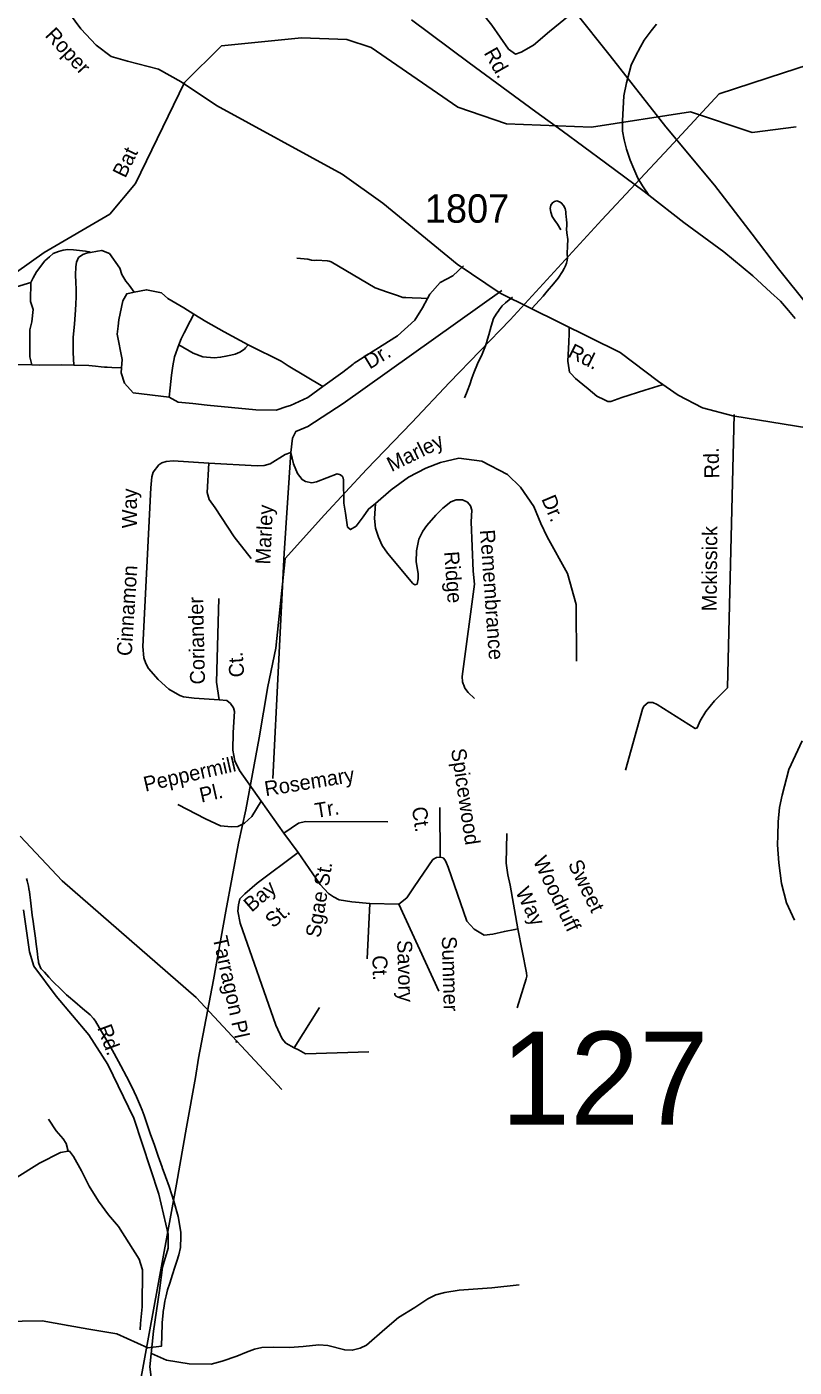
# Model space of a CAD drawing. Extents: x 884530 to 1028605, y 526725 to 653634.
# Drawn here: x 978709 to 982090, y 565783 to 571686 of the extents above; entities that cross this region are included whole.
import ezdxf

# ---------------------------------------------------------------- set-up
doc = ezdxf.new("R2010")
doc.units = 0
for name, color, linetype in [('Exist Boundary Political City Limit New', 7, 'Continuous'), ('Exist Hydrographic Creek Single Shore', 7, 'Continuous'), ('Exist Hydrographic Creek Single Shore Label', 7, 'Continuous'), ('Exist Railroad Mainline', 7, 'Continuous'), ('Exist Road Non-System Type 51', 7, 'Continuous'), ('Exist Road Non-System Type 51 Label', 7, 'Continuous'), ('Exist Road Primary US UnDivided 4 Lane Attributed', 7, 'Continuous'), ('Exist Road Secondary Structure Standard Bridge Number Label', 7, 'Continuous'), ('Exist Road Secondary Type 51 Attributed', 7, 'Continuous'), ('Exist Road Secondary Type 51 Label', 7, 'Continuous'), ('Exist Road Secondary Type 51 Number Label', 7, 'Continuous'), ('Exist Utilities Electrical Transmission Line', 7, 'Continuous'), ('Map Preparation Boundary City Limit Buffer Line', 7, 'Continuous')]:
    doc.layers.add(name, color=color, linetype=linetype)

msp = doc.modelspace()

# ---------------------------------------------------------------- linework, layer by layer
at = {"layer": 'Exist Boundary Political City Limit New'}
for points in [[(979387.1, 566377.1), (979375.6, 566446.4), (979356.9, 566513.9), (979335.4, 566578.2), (979320, 566622.3), (979305.6, 566663), (979305.3, 566663.8), (979287.9, 566712.2), (979269.2, 566764.4), (979253.9, 566808.4), (979239.1, 566852.1), (979225.4, 566891.6), (979216.6, 566914.7), (979209.6, 566933.2), (979192.1, 566974.1), (979171.5, 567017.6), (979148.4, 567062.8), (979123.1, 567110.2), (979093.1, 567164.6), (979065, 567214.5), (979038.2, 567261.5), (979012, 567307), (979002.6, 567319.1), (978987.8, 567334.4), (978953.8, 567363.1), (978920.3, 567392.5), (978891.7, 567414.8), (978883.6, 567422.8), (978861.4, 567444.2), (978821.4, 567483.2), (978805.2, 567501.1), (978785.9, 567523), (978778.8, 567530.7), (978771.4, 567538.1), (978769.3, 567541.8), (978767.4, 567546), (978764.5, 567554), (978762.3, 567560.6), (978760.9, 567565.7), (978759.8, 567571.1), (978758.5, 567578.2), (978757.3, 567586.1), (978755.2, 567603.6), (978753.1, 567625.4), (978750.5, 567646.6), (978746.8, 567673.1), (978739.1, 567723.1), (978736, 567745.3), (978732.4, 567773.7), (978724.8, 567839.8), (978722.2, 567863.7), (978720.5, 567875.9), (978718.3, 567889), (978715.9, 567901.2), (978713.1, 567913.3), (978710.3, 567924.9), (978707.5, 567935.5)], [(978508.9, 565983.2), (978777, 565986.5), (978890.5, 565966.3), (978982.1, 565950), (979105.3, 565930.1), (979242.2, 565868.1), (979301.4, 565875.2), (979303.2, 565923.6), (979305.1, 565972.6), (979305.2, 565977.5), (979309, 566023.9), (979309.3, 566027.6), (979311.7, 566043.1), (979316.4, 566073.2), (979322, 566097.2), (979329.3, 566122.9), (979338.8, 566153.4), (979350.4, 566190.7), (979360.8, 566222.9), (979370.4, 566250.5), (979379.1, 566278.1), (979386, 566310.1), (979386.8, 566358.4), (979387.1, 566374.3), (979387.1, 566377.1)]]:
    msp.add_lwpolyline(points, dxfattribs=at)
at = {"layer": 'Exist Hydrographic Creek Single Shore'}
for points in [[(978596.8, 570558.8), (978785, 570692.8), (979074.3, 570860.9), (979187.5, 570996.4), (979403, 571441.7), (979567.1, 571602.5), (979918.5, 571638.1), (980118.4, 571630.8), (980225.5, 571595.8), (980608.3, 571332.1), (980822.6, 571258.9), (981197.5, 571244.8), (981633.4, 571311.4), (981905.3, 571220.6), (982098.1, 571246.3)], [(979833, 567005.9), (979455.2, 567410.6), (978864.1, 567924.6), (978679.2, 568122)]]:
    msp.add_lwpolyline(points, dxfattribs=at)
at = {"layer": 'Exist Railroad Mainline'}
for points in [[(980403.9, 571717.2), (980657.5, 571528.3), (980952.2, 571311.9), (981067.4, 571227.9), (981258.6, 571087.2), (981428.5, 570961.2), (981449.8, 570944.5), (981603.8, 570825), (981779.4, 570694.8), (981908, 570590.4), (981987.5, 570515.6), (982030.1, 570478.1), (982064.7, 570436.8), (982093.6, 570401.8)], [(981483.9, 571697.9), (981459, 571668.6), (981429.5, 571627.7), (981412.5, 571598.3), (981391.1, 571556.9), (981371.7, 571517.5), (981350.9, 571440.3), (981339, 571382.7), (981333.2, 571272.8), (981333.6, 571226.8), (981340.3, 571188.4), (981350.8, 571148), (981367.3, 571099.4), (981383.9, 571060.9), (981400.5, 571020.1), (981421.2, 570985.5), (981449.8, 570944.5)], [(982125.2, 568541.4), (982066.3, 568414.6), (982037.1, 568301.8), (982025.2, 568248.2)], [(982025.2, 568248.2), (982020, 568184.5), (982018, 568124.5), (982016.8, 568083.7), (982021.8, 568004.4), (982034.1, 567912.8), (982056.4, 567828.6), (982091.1, 567751.8)]]:
    msp.add_lwpolyline(points, dxfattribs=at)
at = {"layer": 'Exist Road Non-System Type 51'}
for p, q in [((979742, 568275.9), (979840.8, 568134.7)), ((980529.3, 568029), (980529.2, 568247.8)), ((979840.8, 568134.7), (979904.6, 568049.5)), ((980220.8, 567824.4), (980207.9, 567581.9)), ((980220.8, 567824.4), (980348, 567822.2)), ((980348, 567822.2), (980523.7, 567438.5)), ((979887.4, 567189.7), (979997.7, 567367))]:
    msp.add_line(p, q, dxfattribs=at)
for points in [[(980934.5, 570445.9), (980968.4, 570482.1), (980983.8, 570499.4), (981002.1, 570521.8), (981028.7, 570553.9), (981049.6, 570579.3), (981069.4, 570609.2), (981076.5, 570621.8), (981082.7, 570633.7), (981087.2, 570645.1), (981089.7, 570657.1), (981090.4, 570670.6), (981089.8, 570687.1), (981090.7, 570721.3), (981092.6, 570749), (981087.8, 570779.4), (981086.1, 570795.6), (981087.8, 570811.1), (981087.8, 570822.7), (981086.1, 570835.9), (981084.7, 570851.3), (981083.9, 570862.9), (981083.2, 570871.5), (981081.5, 570886.1), (981073, 570900.1), (981063.8, 570911.7), (981055.3, 570915.5), (981044.5, 570919.4), (981034.4, 570916.7), (981024.6, 570911.4), (981018, 570901.2), (981015.1, 570886.9), (981017.4, 570870.7), (981022.8, 570851.3), (981035.1, 570832.8), (981046.8, 570816.5), (981062.3, 570792.6)], [(978726.9, 570560.2), (978736.8, 570580.5), (978751.3, 570606.6), (978788.8, 570655.7), (978808.8, 570673.7), (978824.5, 570688), (978847.9, 570697.1), (978868.7, 570703.1), (978889.1, 570705.7), (978914.2, 570704.6), (978940.4, 570701.1), (978966.7, 570697.6), (978974.6, 570696.8), (978984.1, 570695), (978989.5, 570693)], [(978915.9, 570196.1), (978913.4, 570251.5), (978912.4, 570287.3), (978913.1, 570319.9), (978915.6, 570347.5), (978918.9, 570378), (978921.9, 570417.6), (978924.6, 570463), (978926.1, 570498.1), (978925.9, 570530.3), (978924, 570561), (978922.5, 570594.1), (978924.1, 570628.6), (978928, 570650.5), (978937.1, 570669.8), (978955.1, 570684), (978971.5, 570689.9), (978986.4, 570692.5), (978989.5, 570693)], [(978989.5, 570693), (979019.7, 570697.6), (979039.2, 570701.3), (979072.3, 570687.6), (979118.7, 570623.9), (979127.3, 570595), (979144.7, 570566.1), (979160.1, 570548.9), (979181.8, 570517.3)], [(980473.9, 570489.4), (980445.7, 570492), (980406.5, 570492.9), (980378.8, 570493.9), (980371.2, 570493.9), (980365.5, 570494.8), (980342.5, 570502.5), (980298.6, 570517.7), (980243.3, 570536.8), (980049.1, 570650.9), (980040.9, 570654.3), (980032.4, 570656.2), (979986.6, 570658.1), (979975.1, 570657.1), (979963.6, 570658.1), (979947.4, 570662.9), (979897.8, 570667.6)], [(980632.8, 570634), (980585.2, 570589.2), (980530.3, 570560.2), (980483.9, 570508.2), (980473.9, 570489.4)], [(978731, 570197), (978660.4, 570199.8), (978613.4, 570205.4), (978569.3, 570213.7), (978536.8, 570224.4), (978525.2, 570242.3), (978521, 570273.7), (978521.8, 570310.1), (978526.6, 570360.7), (978536.5, 570403.1), (978554.7, 570441.1), (978594.2, 570489), (978644.4, 570528.8), (978663.9, 570540.9), (978726.9, 570560.2)], [(978731, 570197), (978722.4, 570233.4), (978722.4, 570253.6), (978722.4, 570282.5), (978722.4, 570314.4), (978722.4, 570352), (978731, 570386.7), (978736.8, 570441.7), (978725.3, 570476.4), (978725.5, 570510), (978725.8, 570530.6), (978726.9, 570560.2)], [(979126, 570184.7), (979128.1, 570221.4), (979107.3, 570332.9), (979111.1, 570367.3), (979114.2, 570395.7), (979131.6, 570479.4), (979149, 570510.8), (979181.8, 570517.3)], [(979181.8, 570517.3), (979236.2, 570528.2), (979302.4, 570514.3), (979330.4, 570489.9), (979400.1, 570448), (979444.7, 570421)], [(980473.9, 570489.4), (980451.9, 570448.7), (980418.7, 570394.3), (980341.9, 570324.7), (980151.2, 570205.1), (980146.3, 570200.7), (980100.8, 570165.6), (980012.8, 570102.5), (979947.4, 570054.1), (979870.7, 570019.2), (979854.9, 570013.9), (979808, 569998.2), (979717.4, 569999.1), (979503.4, 570019.3), (979439.8, 570028), (979376.1, 570033.8), (979335.8, 570055.8)], [(980802.4, 570524.5), (980103.3, 570027.6), (979947, 569925.7), (979893.9, 569903.6), (979879.4, 569874.7), (979871.4, 569811.4)], [(980848.5, 570495.4), (980818, 570471.2), (980803.6, 570457.6), (980790.4, 570440.6), (980785.3, 570432.6), (980780.4, 570425.4), (980776.7, 570421), (980765.1, 570401.7), (980754.5, 570368.3), (980744, 570330.1), (980738.8, 570311.3), (980733.7, 570294.8), (980729.4, 570281.5), (980714.4, 570245.2), (980695, 570201.6), (980678.5, 570162.3), (980670, 570138.6), (980660.8, 570111.7), (980650.9, 570084.4), (980646.5, 570073.6), (980642.1, 570063), (980637.6, 570052.7)], [(979378.5, 570285.7), (979389.5, 570311.7), (979402.2, 570338.2), (979415, 570363.2), (979421.6, 570376.4), (979428.7, 570390), (979444.7, 570421)], [(979444.7, 570421), (979497.7, 570388.8), (979577.9, 570343.5), (979683.4, 570285.9)], [(981508.7, 570109.6), (981432.5, 570085.8), (981330, 570053.2), (981282.2, 570036.1), (981269.1, 570036.3), (981254.6, 570042.9), (981220.7, 570059.8), (981182.6, 570092), (981158.6, 570111.7), (981126.7, 570137.9), (981105.4, 570158.9), (981099.6, 570165.9), (981097.7, 570175.3), (981093.2, 570214.4), (981097.5, 570297.7), (981099, 570335.4), (981097.8, 570362.2)], [(979335.8, 570055.8), (979340.1, 570096.4), (979343.2, 570124.2), (979346.6, 570152.1), (979351.9, 570192.7), (979359.9, 570232.4), (979378.5, 570285.7)], [(979683.4, 570285.9), (979672.7, 570272.8), (979667.6, 570266.9), (979647.8, 570252.8), (979627.2, 570244.8), (979607.4, 570240.1), (979586, 570235.6), (979562.5, 570231.1), (979534.5, 570228.1), (979483.6, 570232.5), (979441.8, 570248.5), (979378.5, 570285.7)], [(979683.4, 570285.9), (979692.9, 570280.7), (979828.9, 570214.4), (979860.2, 570193.5), (980012.8, 570102.5)], [(978915.9, 570196.1), (978862.2, 570197.7), (978764.5, 570195.7), (978731, 570197)], [(979126, 570184.7), (979083.9, 570186.6), (979062.6, 570187.5), (979050.4, 570188.1), (979036, 570189.4), (979011, 570191.6), (978981.4, 570194.1), (978915.9, 570196.1)], [(979335.8, 570055.8), (979176.9, 570075), (979138.7, 570116.8), (979124.6, 570162.1), (979126, 570184.7)], [(981825.8, 569978.3), (981798.9, 568899.9), (981795.8, 568775), (981739, 568718), (981699.9, 568671.1), (981675.9, 568629.7), (981662.8, 568599.2), (981653.9, 568595.3), (981486.2, 568702.1), (981467, 568711), (981446.4, 568710.8), (981428, 568693.6), (981422, 568680.6), (981346.3, 568412.2)], [(979510.7, 569765), (979353.7, 569774.6), (979322.4, 569772.3), (979302.9, 569765.5), (979290.2, 569756.5), (979264.7, 569724.4), (979259.7, 569703.9), (979255.6, 569656.3), (979219.5, 568957.8), (979224.3, 568907.7), (979233, 568882.9), (979245.5, 568859.6), (979287.5, 568811.5), (979334.6, 568769), (979382.5, 568740.9), (979399.7, 568734.7), (979445.4, 568729), (979556.1, 568722.4)], [(979510.7, 569765), (979502.9, 569635.8), (979511.9, 569605.2), (979538.1, 569567.1), (979622, 569440.8), (979697.2, 569345.3)], [(979871.4, 569811.4), (979847.7, 569802.7), (979780.6, 569761.1), (979754.5, 569753.8), (979724.3, 569753.2), (979510.7, 569765)], [(979871.4, 569811.4), (979842.6, 569367.9), (979792.3, 568375.6)], [(979871.4, 569811.4), (979883.6, 569762.1), (979901.2, 569718.6), (979921.7, 569692.1), (979936.5, 569684.1), (979964.1, 569678.4), (979985.2, 569682.3), (980076.6, 569717.7), (980090.2, 569713.9), (980100.5, 569704.3), (980104.7, 569690.9), (980105.2, 569588), (980112.9, 569544.9), (980121.5, 569482.8), (980134.3, 569472.1), (980160, 569487.1), (980190.1, 569527.8), (980213.7, 569562.2), (980245.2, 569587.1)], [(980245.2, 569587.1), (980313.8, 569647.1), (980390.7, 569702.5), (980466.5, 569743.1), (980531.5, 569768.2), (980612.9, 569786.4), (980713.9, 569772.9), (980826.1, 569714.6), (980884.5, 569658.4), (980942.8, 569573.2), (980974.2, 569499.1), (981001.2, 569440.8), (981091, 569279.2), (981129.1, 569142.3), (981131.4, 568893.2)], [(980245.2, 569587.1), (980240.7, 569520.9), (980244.6, 569477.8), (980257.7, 569439.3), (980274, 569401.4), (980297.5, 569368.1), (980409.3, 569234.8), (980417.7, 569228.3), (980428, 569231.8), (980432.6, 569254.7), (980432.9, 569278), (980423.7, 569330.2), (980425.8, 569378.4), (980435.7, 569430.5), (980453.1, 569465.2), (980471.3, 569489.3), (980510.4, 569536), (980541.8, 569566.5), (980577.2, 569594.1), (980600.2, 569602.6), (980628.9, 569603.8), (980650.3, 569593.2), (980663.4, 569576.8), (980670.2, 569557.4), (980666.1, 569506.1), (980674.9, 569288.9), (980681.6, 569232.1), (980627, 568825.2), (980628.8, 568801.9), (980630.8, 568792.2), (980634.2, 568786.7), (980638.7, 568773.4), (980653.4, 568754.2), (980681.6, 568727.5)], [(979556.1, 568722.4), (979544, 568799.8), (979554.9, 569168.8)], [(979556.1, 568722.4), (979590.1, 568718.8), (979605.7, 568705.8), (979618.7, 568686.8), (979623.2, 568670.7), (979617.4, 568577.6), (979616.3, 568500.8), (979625.3, 568453.1), (979645.8, 568411.1), (979742, 568275.9)], [(979742, 568275.9), (979700.6, 568207.9), (979668.4, 568179.1), (979639.1, 568164.9), (979610.8, 568162.2), (979561.7, 568167.3), (979495.6, 568197.8), (979373.7, 568260.5)], [(979840.8, 568134.7), (979906.3, 568178.5), (979936.7, 568186.4), (980299.2, 568184.2)], [(980872.5, 567712.9), (980838.1, 567905.8), (980827.5, 567950.8), (980820.6, 568003.4), (980823.8, 568133.7)], [(979904.6, 568049.5), (979723.4, 567914.2), (979668.8, 567868.2), (979646.6, 567845.1), (979641.4, 567818.6), (979639.1, 567791.3), (979649, 567739.1), (979805.7, 567288.9), (979833.8, 567229.1), (979850.1, 567210.6), (979887.4, 567189.7)], [(979904.6, 568049.5), (980001.2, 567909.4), (980038, 567869.3), (980060.3, 567854.2), (980085, 567840.6), (980141.1, 567832), (980220.8, 567824.4)], [(980348, 567822.2), (980383.5, 567850.3), (980414.8, 567898.8), (980497.9, 568018.4), (980513.2, 568027.2), (980529.3, 568029)], [(980529.3, 568029), (980543, 568026.7), (980552.1, 568015.5), (980558.4, 568002.3), (980564.8, 567985.8), (980648.2, 567747.8), (980679.5, 567712.2), (980723.7, 567686.3), (980762.5, 567690.6), (980813.1, 567702.5), (980859.5, 567710.1), (980872.5, 567712.9)], [(980872.5, 567712.9), (980910.3, 567519.9), (980911.5, 567504.6), (980909.1, 567492.8), (980868.9, 567366.1)], [(979887.4, 567189.7), (979905.5, 567180.2), (979936.8, 567163), (980215.9, 567172.4)], [(978890.9, 566733.6), (978882.1, 566768.3), (978868.8, 566788.2), (978837.9, 566823.6), (978804.5, 566874.6)], [(977930.5, 566469.9), (977998.8, 566478.2), (978040.7, 566484), (978109.3, 566481), (978154, 566478.1), (978201.7, 566475), (978267.6, 566471.2), (978338.9, 566472.1), (978370.3, 566476.7), (978404.5, 566487), (978482, 566525.7), (978598.1, 566582.4), (978654.8, 566612.2), (978765.2, 566680.8), (978857.5, 566728.4), (978890.9, 566733.6)], [(978890.9, 566733.6), (978896.3, 566734.4), (978914.2, 566710.5), (978950, 566648), (978982.8, 566579.4), (979024.5, 566513.8), (979069.3, 566454.2), (979112.5, 566402.2), (979204, 566258.8), (979210.2, 566240.1), (979218.5, 566211), (979216.5, 566048.9), (979210.2, 565975.9), (979208, 565947.1)], [(979258.2, 565842.9), (979324.3, 565813.5), (979424.2, 565798), (979521.4, 565796.6), (979569.9, 565808.7), (979634.2, 565830.7), (979676.4, 565849.3), (979711.9, 565862.8), (979744.9, 565869.6), (979794.8, 565870.4), (979865.9, 565869.6), (979926.8, 565873.8), (979996.1, 565881.4), (980034.9, 565878.9), (980109.4, 565858.6), (980142.4, 565857.7), (980177.1, 565867.1), (980204.9, 565880.5), (980286.1, 565950), (980347, 566002.3), (980418.9, 566046.3), (980476.3, 566084.4), (980511.1, 566102.1), (980549.9, 566112.3), (980613.4, 566122.5), (980757.1, 566132.6), (980878.8, 566145.3)]]:
    msp.add_lwpolyline(points, dxfattribs=at)
at = {"layer": 'Exist Road Primary US UnDivided 4 Lane Attributed'}
msp.add_lwpolyline([(981122, 571754.9), (981278.7, 571558.2), (981524.1, 571245.3), (981739.5, 570988.5), (981904.2, 570772.5), (982021, 570620.5), (982151.6, 570457.9), (982245.3, 570336.5), (982331.4, 570219.4), (982446.1, 570096.4), (982519.7, 570004), (982626.5, 569820.7)], dxfattribs=at)
at = {"layer": 'Exist Road Secondary Type 51 Attributed'}
for points in [[(982319.2, 569872.7), (982155, 569918.8), (981819.3, 569973.6), (981685.7, 570008.4), (981579, 570063.9), (981491.5, 570124.4), (981323, 570251.8), (980794.5, 570512.8), (980604.9, 570641.4), (980277.8, 570909.2), (980098.6, 571037.3), (979544, 571340.4), (979388.9, 571444.6), (979289.1, 571500), (979152.4, 571535.2), (979080.3, 571555.5), (979013.8, 571605.4), (978946.7, 571677.7), (978806.2, 571870.6), (978705.3, 571952.9), (978614.7, 572013.9), (978515, 572049)], [(980551.2, 571958.9), (980589.3, 571905.5), (980712.6, 571750.3), (980758, 571693.8), (980831.5, 571588.4), (980861.3, 571566.5), (980887.2, 571574.5), (980940.9, 571606.3), (981012.4, 571666), (981122, 571754.9)], [(978693.8, 567797.4), (978720.9, 567612.8), (978739.8, 567548.8), (978838.1, 567417.2), (978982.4, 567247.1), (979065.3, 567115.6), (979180.1, 566879.2), (979290.1, 566544.3), (979331.6, 566368.3), (979331.6, 566307), (979305.9, 566223.9), (979292.7, 566119.9), (979266.3, 565941.1), (979250.5, 565784.1), (979264.4, 565681.2)]]:
    msp.add_lwpolyline(points, dxfattribs=at)
at = {"layer": 'Exist Utilities Electrical Transmission Line'}
msp.add_lwpolyline([(982255.4, 571553.1), (982043, 571484.4), (981759.7, 571392), (981539.2, 571153.6), (981241.9, 570835.7), (980838.4, 570395.3), (980570.8, 570120.4), (980404.6, 569943.9), (980205.4, 569736.6), (980020.3, 569536.9), (979847.4, 569344.7), (979805.8, 568950), (979770, 568781.1), (979732, 568554.2), (979673.1, 568238.1), (979641.9, 568091.1), (979585.4, 567790.7), (979531, 567488.5), (979465.2, 567144.5), (979452.1, 567058.8), (979412.5, 566840.1), (979367.8, 566589.5), (979207.2, 565706.5)], dxfattribs=at)
at = {"layer": 'Map Preparation Boundary City Limit Buffer Line'}
for points in [[(979387.1, 566377.1), (979375.6, 566446.4), (979356.9, 566513.9), (979335.4, 566578.2), (979320, 566622.3), (979305.6, 566663), (979305.3, 566663.8), (979287.9, 566712.2), (979269.2, 566764.4), (979253.9, 566808.4), (979239.1, 566852.1), (979225.4, 566891.6), (979216.6, 566914.7), (979209.6, 566933.2), (979192.1, 566974.1), (979171.5, 567017.6), (979148.4, 567062.8), (979123.1, 567110.2), (979093.1, 567164.6), (979065, 567214.5), (979038.2, 567261.5), (979012, 567307), (979002.6, 567319.1), (978987.8, 567334.4), (978953.8, 567363.1), (978920.3, 567392.5), (978891.7, 567414.8), (978883.6, 567422.8), (978861.4, 567444.2), (978821.4, 567483.2), (978805.2, 567501.1), (978785.9, 567523), (978778.8, 567530.7), (978771.4, 567538.1), (978769.3, 567541.8), (978767.4, 567546), (978764.5, 567554), (978762.3, 567560.6), (978760.9, 567565.7), (978759.8, 567571.1), (978758.5, 567578.2), (978757.3, 567586.1), (978755.2, 567603.6), (978753.1, 567625.4), (978750.5, 567646.6), (978746.8, 567673.1), (978739.1, 567723.1), (978736, 567745.3), (978732.4, 567773.7), (978724.8, 567839.8), (978722.2, 567863.7), (978720.5, 567875.9), (978718.3, 567889), (978715.9, 567901.2), (978713.1, 567913.3), (978710.3, 567924.9), (978707.5, 567935.5)], [(978508.9, 565983.2), (978777, 565986.5), (978890.5, 565966.3), (978982.1, 565950), (979105.3, 565930.1), (979242.2, 565868.1), (979301.4, 565875.2), (979303.2, 565923.6), (979305.1, 565972.6), (979305.2, 565977.5), (979309, 566023.9), (979309.3, 566027.6), (979311.7, 566043.1), (979316.4, 566073.2), (979322, 566097.2), (979329.3, 566122.9), (979338.8, 566153.4), (979350.4, 566190.7), (979360.8, 566222.9), (979370.4, 566250.5), (979379.1, 566278.1), (979386, 566310.1), (979386.8, 566358.4), (979387.1, 566374.3), (979387.1, 566377.1)]]:
    msp.add_lwpolyline(points, dxfattribs=at)

# ---------------------------------------------------------------- texts
at = {"layer": 'Exist Hydrographic Creek Single Shore Label'}
msp.add_text('Bat', height=65.62, rotation=64.17315, dxfattribs=at).set_placement((979142.7, 571016.8))
msp.add_text('Bat', height=65.62, rotation=64.17315, dxfattribs=at).set_placement((979142.7, 571016.8))
at = {"layer": 'Exist Road Non-System Type 51 Label'}
for s, height, rotation, p in [('Dr.', 65.62, 31.25004, (980219.6, 570176.5)), ('Marley', 65.62, 26.00999, (980315.5, 569724.9)), ('Rd.', 65.62, 91.22388, (981759.9, 569697.8)), ('Way', 65.62, 89.80077, (979193.5, 569477.8)), ('Dr.', 65.62, 292.93084, (980974.8, 569607.3)), ('Marley', 65.62, 87.18442, (979780.9, 569317)), ('Mckissick', 65.62, 89.52353, (981748.3, 569112.2)), ('Remembrance', 65.617, 274.03313, (980705.1, 569469.8)), ('Ridge', 65.62, 274.03313, (980547.4, 569374.3)), ('Cinnamon', 65.62, 86.35401, (979170.5, 568913.6)), ('Coriander', 65.62, 91.31728, (979494.2, 568790.5)), ('Ct.', 65.62, 94.01626, (979667.3, 568823.5)), ('Peppermill', 65.62, 12.76797, (979231, 568317.4)), ('Spicewood', 65.62, 278.60856, (980577.3, 568503.5)), ('Rosemary', 65.62, 9.28018, (979761.4, 568297.2)), ('Pl.', 65.62, 12.76797, (979477.6, 568269.1)), ('Tr.', 65.62, 9.28018, (979983.5, 568201.3)), ('Ct.', 65.62, 278.60856, (980404.8, 568246.7)), ('Sgae St.', 65.62, 80.76155, (980001.5, 567671.8)), ('Woodruff', 65.62, 295.84751, (980937.3, 568014.2)), ('Sweet', 65.62, 295.84751, (981091.5, 567998.7)), ('Bay', 65.62, 40.73453, (979699.1, 567784.1)), ('Way', 65.62, 295.84751, (980860, 567877.8)), ('St.', 65.62, 40.73453, (979793.9, 567714.2)), ('Tarragon Pl.', 65.617, 282.42949, (979527.4, 567674.5)), ('Savory', 65.62, 271.5063, (980340.4, 567663.3)), ('Summer', 65.62, 271.5063, (980537.1, 567680.4)), ('Ct.', 65.62, 271.5063, (980231.2, 567596.3))]:
    msp.add_text(s, height=height, rotation=rotation, dxfattribs=at).set_placement(p)
at = {"layer": 'Exist Road Secondary Structure Standard Bridge Number Label'}
msp.add_text('127', height=410.1, dxfattribs=at).set_placement((980797.2, 566850.7))
at = {"layer": 'Exist Road Secondary Type 51 Label'}
for s, rotation, p in [('Roper', 312.88522, (978785.4, 571646.2)), ('Rd.', 299.61605, (980720.4, 571571.8)), ('Rd.', 333.3533, (981088.5, 570235.5)), ('Rd.', 290.24192, (979018.2, 567278.2))]:
    msp.add_text(s, height=65.62, rotation=rotation, dxfattribs=at).set_placement(p)
at = {"layer": 'Exist Road Secondary Type 51 Number Label'}
msp.add_text('1807', height=125, dxfattribs=at).set_placement((980462.5, 570823.6))

doc.saveas('drawing.dxf')
